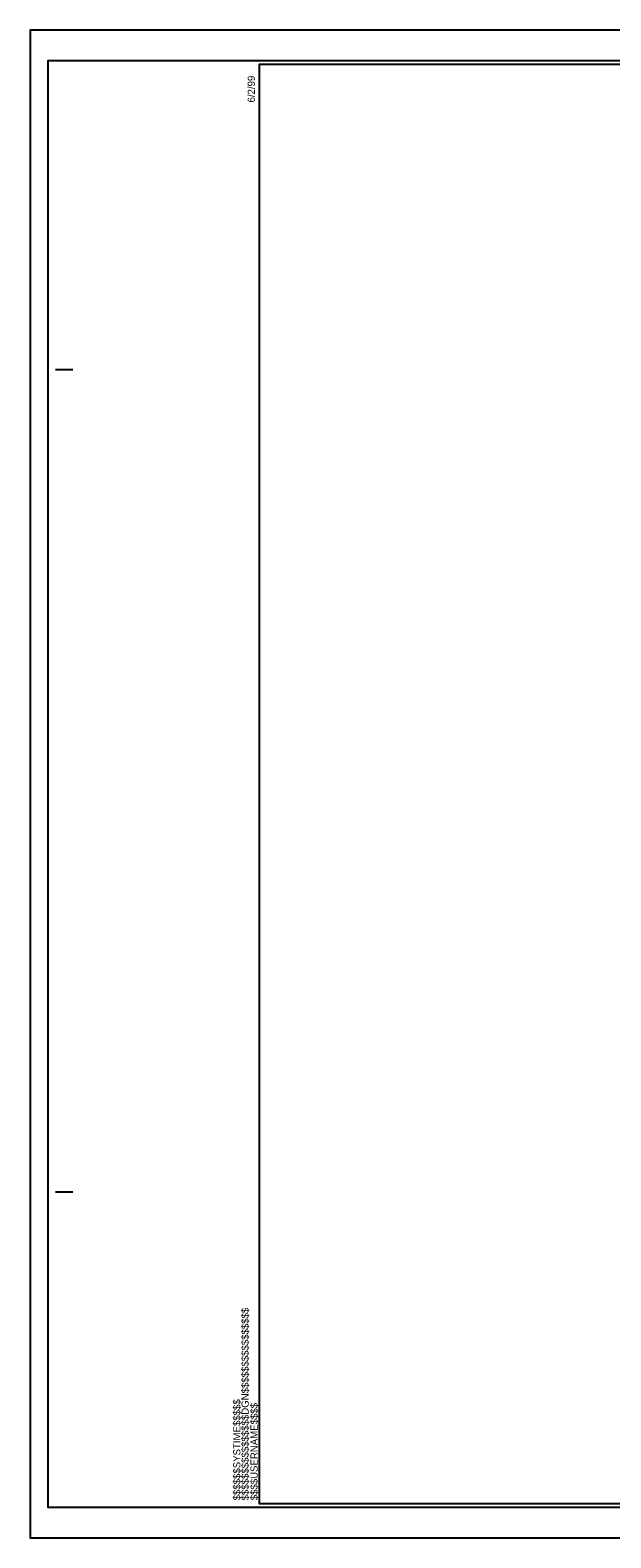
# Model space of a CAD drawing. Extents: x 106738.7 to 106779.9, y 105993.5 to 106034.9.
# Drawn here: x 106738.68 to 106747.14, y 106012.88 to 106034.88 of the extents above; entities that cross this region are included whole.
import ezdxf

# ---------------------------------------------------------------- set-up
doc = ezdxf.new("R2010")
doc.units = 0
for name, color, linetype in [('Sheet Cutting Line CELL', 7, 'Continuous'), ('Sheet Plot Border Inside CELL', 7, 'Continuous'), ('Sheet Plot Border Outside CELL', 7, 'Continuous'), ('Sheet Typical CELL', 7, 'Continuous')]:
    doc.layers.add(name, color=color, linetype=linetype)

msp = doc.modelspace()

# ---------------------------------------------------------------- linework, layer by layer
at = {"layer": 'Sheet Cutting Line CELL'}
for p, q in [((106772.356, 106034.882), (106738.676, 106034.882)), ((106738.676, 106034.882), (106738.676, 106012.882)), ((106738.676, 106012.882), (106772.356, 106012.882))]:
    msp.add_line(p, q, dxfattribs=at)
at = {"layer": 'Sheet Plot Border Inside CELL'}
msp.add_lwpolyline([(106772.266, 106034.433), (106738.936, 106034.433), (106738.936, 106013.331), (106772.266, 106013.331)], close=True, dxfattribs=at)
at = {"layer": 'Sheet Plot Border Outside CELL'}
msp.add_lwpolyline([(106772.356, 106034.882), (106738.676, 106034.882), (106738.676, 106012.882), (106772.356, 106012.882)], close=True, dxfattribs=at)
at = {"layer": 'Sheet Typical CELL'}
for p, q in [((106739.046, 106029.932), (106739.296, 106029.932)), ((106739.046, 106017.932), (106739.296, 106017.932)), ((106742.016, 106013.382), (106742.016, 106013.382)), ((106742.016, 106013.382), (106742.016, 106013.382)), ((106742.016, 106013.382), (106742.016, 106013.382)), ((106742.016, 106013.382), (106742.016, 106013.382)), ((106742.016, 106013.382), (106742.016, 106013.382)), ((106742.016, 106013.382), (106742.016, 106013.382))]:
    msp.add_line(p, q, dxfattribs=at)
msp.add_lwpolyline([(106772.016, 106034.382), (106742.016, 106034.382), (106742.016, 106013.382), (106772.016, 106013.382)], close=True, dxfattribs=at)
msp.add_lwpolyline([(106742.766, 106013.382), (106742.766, 106013.382)], dxfattribs=at)

# ---------------------------------------------------------------- texts
for s, p in [('6/2/99', (106741.953, 106033.827)), ('$$$$$$$$$$$$$$$$DGN$$$$$$$$$$$$$$$$', (106741.863, 106013.429)), ('$$$$$$SYSTIME$$$$$', (106741.742, 106013.429)), ('$$$$USERNAME$$$$', (106741.994, 106013.43))]:
    msp.add_text(s, height=0.105, rotation=90, dxfattribs=at).set_placement(p)

doc.saveas('drawing.dxf')
